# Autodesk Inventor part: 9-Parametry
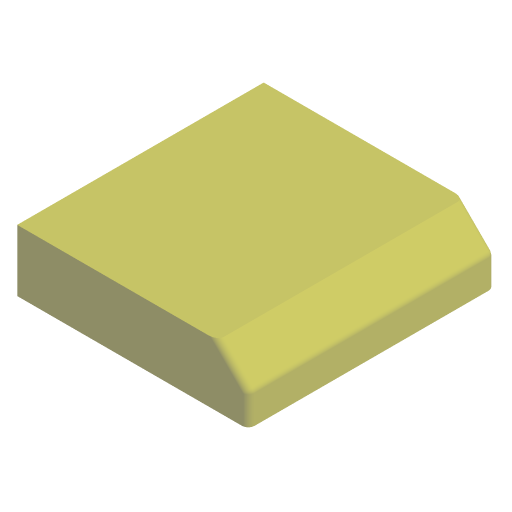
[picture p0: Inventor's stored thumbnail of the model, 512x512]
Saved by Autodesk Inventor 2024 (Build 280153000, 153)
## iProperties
Company: ATC
Shininess: 0.0
Length Units: 11269
Angle Units: 11279
Time Units: 11290
Mass Units: 11283
Length Display Precision: 3
Angle Display Precision: 2
Compacted: True
Created: 2023-03
Part Number: 9-Parametry
Document SubType Name: Modeling
Designer: Andrzej Jaskulski
Material: Kurs-AJ
Density: 1 g/cm^3
Appearance: Przezroczyste — żółte
Checked By: A.J.
Engr Approved By: Andrzej Jaskulski
Mfg Approved By: Andrzej Jaskulski
Authority: A.J.
Density: 0.0
Volumn: 0.0
Area: 0.0
PropertySet Name: Model Information
Control State: 0
Master: False
Checked Out: False
Title: A.J.: Kurs R2024-MEP
Author: Andrzej Jaskulski
Revision Number: 1/24
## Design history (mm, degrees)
node "Extrusion1" dims "d0" = 0, "d1" = 20
  sketch "Sketch1"
    geometry: L1 (-60, 0)-(20, 0); L2 (20, 0)-(20, 75) reference; L3 (20, 75)-(-60, 75) reference; L4 (-60, 75)-(-60, 0)
    constraints: 8 end point, 2 parallel, 1 horizontal, 1 perpendicular, 1 vertical
    dimensions: "d3" = 80 distance of L1.start L1.end; "d2" = 75 distance of L1.end L2.end; "d6" = 109.65856 distance of L1.start L2.end (derived)
node "Chamfer1" dims "d4" = 10, "d5" = 10, "d30" = 45 deg
node "Fillet1" dims "R" = 2
node "Bryła1"
node "Korpusy bryłowe"
node "Korpusy powierzchniowe"
